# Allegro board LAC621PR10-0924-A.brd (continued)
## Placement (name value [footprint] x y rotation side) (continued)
PC5  -  [C_0805]  34.94 87.39 0 top
PC6  -  [C_0603]  38.95 87.3 270 top
PC7  -  [C_0805]  38.82 84.46 0 top
PC8  -  [C_0402]  277.09 10.93 0 top
PC100  -  [C_0402]  225.92 71.3 180 bottom
PC101  -  [C_0402]  229.78 64.7 0 top
PC102  -  [C_0603]  215.91 73.87 180 bottom
PC103  -  [C_0402]  225.92 71.3 180 top
PC104  -  [C_0805]  226.1 72.67 180 bottom
PC105  -  [C_0805]  226.1 72.67 180 top
PC106  -  [C_0805]  208.67 68.48 180 top
PC107  -  [C_0805]  208.67 71.96 180 top
PC108  -  [C_0805]  208.69 70.21 180 top
PC109  -  [C_0805]  208.7 70.21 180 bottom
PC110  -  [C_0805]  208.67 71.96 180 bottom
PC111  -  [C_0603]  219.42 68.23 270 bottom
PC112  -  [C_0603]  217.44 69.63 90 top
PC113  -  [C_0402]  221.34 68.38 0 bottom
PC114  -  [C_0603]  219.11 65.03 270 bottom
PC115  -  [C_0402]  227.49 64.62 270 bottom
PC116  -  [C_0402]  227.49 64.62 270 top
PC117  -  [C_0805]  226.2 65.21 270 bottom
PC118  -  [C_0805]  226.2 65.21 270 top
PC119  -  [C_0603]  220.31 58.93 270 bottom
PC120  -  [C_0805]  207.38 59.73 270 bottom
PC121  -  [C_0805]  211.03 59.74 270 top
PC122  -  [C_0805]  209.25 59.75 270 bottom
PC123  -  [C_0805]  209.24 59.75 270 top
PC124  -  [C_0805]  207.38 59.74 270 top
PC125  -  [C_0603]  218.83 59.74 90 top
PC126  -  [C_0603]  221.53 58.93 270 bottom
PC127  -  [C_0402]  222.97 58.98 0 bottom
PC128  -  [C_0402]  226.68 59.36 270 bottom
PC201  -  [C_0805]  85.94 55.74 270 top
PC202  -  [C_0805]  84.16 55.74 270 top
PC203  -  [C_0402]  82.76 55.6 270 top
PC204  -  [C_0402]  81.75 55.6 270 top
PC205  -  [C_0603]  87.36 53.06 0 bottom
PC206  -  [C_0603]  90.78 57.53 0 bottom
PC207  -  [C_0603]  92.7 49.29 90 bottom
PC209  -  [C_0603]  96.28 50.82 270 bottom
PC210  -  [C_0402]  91.6 56.75 270 top
PC211  -  [C_0603]  82.47 50.52 0 bottom
PC212  -  [C_0402]  93.28 59.47 180 bottom
PC213  -  [C_0402]  92.39 58.63 90 top
PC214  -  [C_0402]  95.41 53.04 0 bottom
PC215  -  [C_0603]  72.86 50.88 0 bottom
PC216  -  [C_0603]  72.86 48.34 0 top
PC217  -  [C_0603]  72.86 49.61 0 top
PC218  -  [C_0603]  72.86 48.34 0 bottom
PC219  -  [C_0603]  72.86 50.88 0 top
PC220  -  [C_0603]  72.86 49.61 0 bottom
PC301  -  [C_0402]  225.61 57.2 180 bottom
PC302  -  [C_0603]  221.59 55.58 0 bottom
PC303  -  [C_0402]  225.61 57.2 180 top
PC304  -  [C_0603]  226.45 52.34 90 top
PC305  -  [C_0805]  225.77 55.86 180 top
PC306  -  [C_0805]  225.77 55.86 180 bottom
PC307  -  [C_0402]  227.11 48.72 90 bottom
PC308  -  [C_0805]  212.97 51.02 270 bottom
PC309  -  [C_0805]  212.97 51.02 270 top
PC310  -  [C_0805]  211.14 51.01 270 bottom
PC311  -  [C_0805]  211.14 51.01 270 top
PC312  -  [C_0603]  227.29 50.73 270 top
PC313  -  [C_0603]  224.73 49.63 270 top
PC401  -  [C_0402]  200.82 49.69 0 bottom
PC402  -  [C_0402]  205.22 51.36 90 top
PC403  -  [C_0603]  206.68 52.93 270 bottom
PC404  -  [C_0603]  206.68 52.93 270 top
PC406  -  [C_0603]  199.07 56.68 90 bottom
PC407  -  [C_0603]  200.3 56.73 90 bottom
PC408  -  [C_0402]  207.84 53.06 270 top
PC409  -  [C_0402]  207.84 53.05 270 bottom
PC410  -  [C_0402]  204.18 59.38 90 bottom
PC411  -  [C_0402]  203.24 71.15 180 top
PC412  -  [C_0603]  202.52 74.03 0 top
PC413  -  [C_0603]  202.53 74.02 0 bottom
PC415  -  [C_0603]  202.83 63.81 270 bottom
PC416  -  [C_0603]  201.58 63.83 270 bottom
PC417  -  [C_0402]  202.78 75.09 0 bottom
PC418  -  [C_0402]  202.77 75.09 0 top
PC419  -  [C_0402]  204.41 69.07 90 bottom
PC420  -  [C_0402]  198.33 72.39 270 bottom
PC422  -  [C_0603]  200.04 56.7 90 top
PC424  -  [C_0603]  204.06 63.81 270 bottom
PC501  -  [C_0603]  213.87 103.81 0 bottom
PC502  -  [C_0603]  209.27 103.72 0 top
PC503  -  [C_0402]  208.47 101.62 90 bottom
PC504  -  [C_0603]  213.86 103.81 0 top
PC505  -  [C_0402]  208.97 109.06 90 bottom
PC506  -  [C_0402]  211.24 109.01 180 bottom
PC507  -  [C_0402]  217.82 105.98 90 bottom
PC508  -  [C_0805]  222.23 101.29 270 bottom
PC509  -  [C_0402]  219.82 96.43 90 bottom
PC510  -  [C_0402]  219.09 103.84 0 top
PC511  -  [C_0805]  214.88 98.75 90 bottom
PC601  -  [C_0402]  80.15 72.5 90 top
PC602  -  [C_0402]  72.88 68.38 0 top
PC603  -  [C_0603]  79.46 65.51 0 bottom
PC604  -  [C_0603]  79.49 66.76 0 bottom
PC605  -  [C_0402]  75.02 64.72 0 bottom
PC606  -  [C_D]  86.2 72.72 180 bottom
PC608  -  [C_0805]  104 81.17 90 top
PC611  -  [C_0603]  102.89 79.58 180 bottom
PC612  -  [C_0805]  105.78 81.17 90 top
PC613  -  [C_0402]  80 63.96 270 bottom
PC614  -  [C_0402]  82.66 64.85 270 bottom
PC616  -  [C_0402]  81.77 64.85 270 bottom
PC617  -  [C_0402]  77.53 59.64 90 bottom
PC618  -  [C_0402]  77.53 59.64 0 top
PC619  -  [C_0402]  77.53 60.53 0 top
PC620  -  [C_0402]  79.31 59.64 90 top
PC621  -  [C_0402]  76.64 61.42 0 bottom
PC622  -  [C_0603]  109.52 83.42 180 top
PC624  -  [C_0402]  81.19 60.33 90 top
PC625  -  [C_0402]  84.44 64.85 0 bottom
PC626  -  [C_0402]  82.08 60.33 90 top
PC627  -  [C_0402]  82.97 60.33 90 bottom
PC628  -  [C_0402]  81.11 70.69 90 top
PC629  -  [C_0402]  84.47 67.57 270 bottom
PC630  -  [C_0402]  87.84 67.26 270 bottom
PC631  -  [C_0402]  82.89 71.58 180 top
PC632  -  [C_0402]  75.91 70.69 90 bottom
PC633  -  [C_0402]  75.02 70.69 90 top
PC636  -  [C_0402]  85.41 67.57 270 bottom
PC637  -  [C_0402]  75.91 70.69 90 top
PC639  -  [C_0402]  87.84 63.71 0 bottom
PC640  -  [C_0402]  77.48 73.38 270 top
PC641  -  [C_0402]  83.55 63.07 90 bottom
PC642  -  [C_0402]  88.73 66.37 90 top
PC643  -  [C_0402]  83.55 68.66 270 bottom
PC644  -  [C_0402]  74.13 72.47 0 top
PC645  -  [C_0402]  88.73 68.15 180 bottom
PC646  -  [C_0402]  87.84 66.37 90 top
PC647  -  [C_0402]  88.73 65.49 270 top
PC649  -  [C_0402]  81.77 68.66 270 bottom
PC650  -  [C_0402]  78.37 71.61 180 top
PC651  -  [C_0402]  88.73 64.6 180 bottom
PC652  -  [C_0402]  82.66 68.66 270 bottom
PC653  -  [C_0402]  87.84 64.6 90 top
PC654  -  [C_0402]  88.73 65.49 180 bottom
PC655  -  [C_0603]  86.38 77.17 0 bottom
PC656  -  [C_0805]  89.03 71.84 0 top
PC657  -  [C_0805]  89.03 70.06 0 bottom
PC658  -  [C_0805]  89.03 71.84 0 bottom
PC659  -  [C_0402]  89.42 69.65 0 top
PC660  -  [C_0402]  89.42 70.54 0 top
PC661  -  [C_0402]  94.45 76.79 0 bottom
PC662  -  [C_0603]  93.41 71.86 180 bottom
PC671  -  [C_0603]  92 68 0 bottom
PC672  -  [C_0805]  95.43 62.74 0 bottom
PC673  -  [C_0805]  95.43 62.74 0 top
PC677  -  [C_0402]  101.08 67.73 0 bottom
PC678  -  [C_0603]  101.92 66.69 180 bottom
PC679  -  [C_0402]  95.31 61.34 0 bottom
PC680  -  [C_0402]  89.17 73.23 0 top
PC685  -  [C_0402]  100.6 83.62 270 top
PC686  -  [C_0402]  89.17 74.12 0 top
PC688  -  [C_0402]  95.31 61.34 0 top
PC801  -  [C_0805]  71.21 77.93 270 top
PC802  -  [C_0603]  42.2 77.12 270 top
PC803  -  [C_0805]  79.59 77.93 270 top
PC804  -  [C_0805]  83.15 77.93 270 top
PC805  -  [C_0805]  79.59 77.93 270 bottom
PC806  -  [C_0805]  81.37 77.93 270 top
PC807  -  [C_0805]  81.37 77.93 270 bottom
PC808  -  [C_0603]  60.79 87.71 180 top
PC809  -  [C_0402]  57.49 87.96 270 bottom
PC810  -  [C_0402]  59.4 86.57 0 top
PC811  -  [C_0805]  77.81 77.93 270 top
PC812  -  [C_0805]  83.15 77.93 270 bottom
PC813  -  [C_0603]  63.21 84.28 0 bottom
PC814  -  [C_0805]  59.27 84.54 270 bottom
PC815  -  [C_0402]  59.4 89.74 0 top
PC816  -  [C_0402]  60.03 77.8 90 top
PC817  -  [C_0402]  59.02 77.8 90 top
PC818  -  [C_0805]  57.36 77.42 90 top
PC819  -  [C_0805]  57.78 77.47 90 bottom
PC820  -  [C_0805]  56.01 77.47 90 bottom
PC821  -  [C_0603]  60.79 84.15 270 bottom
PC822  -  [C_0805]  55.59 77.42 90 top
PC823  -  [C_0402]  59.26 90.65 90 top
PC824  -  [C_0402]  60.16 90.63 90 top
PC825  -  [C_0603]  76.29 78.06 270 top
PC826  -  [C_0805]  74.76 77.93 270 top
PC827  -  [C_0805]  72.99 77.93 270 top
PC828  -  [C_0603]  69.15 89.98 90 bottom
PC829  -  [C_0402]  68.41 86.06 180 bottom
PC830  -  [C_0402]  66.64 86.06 90 bottom
PC831  -  [C_0402]  67.52 86.95 0 bottom
PC832  -  [C_0603]  61.56 78.06 90 top
PC833  -  [C_0402]  61.58 93.3 90 top
PC834  -  [C_0402]  62.44 94.19 270 top
PC901  -  [C_0402]  29.63 81 180 bottom
PC902  -  [C_0805]  119.86 101.48 0 top
PC903  -  [C_0402]  255.18 95.25 180 top
PC904  -  [C_0402]  76.88 25.05 90 top
PC905  -  [C_0402]  72.35 10.75 90 top
PC906  -  [C_0603]  22.87 76.38 270 top
PC907  -  [C_0603]  29.6 79.96 180 bottom
PC908  -  [C_0603]  25.87 75.71 270 bottom
PC1001  -  [C_0603]  114.51 77.23 90 bottom
PC1002  -  [C_0603]  115.91 70.88 90 top
PC1003  -  [C_0603]  114.51 74.06 90 bottom
PC1004  -  [C_0603]  113.12 74.06 90 top
PC1005  -  [C_0603]  114.51 77.23 90 top
PC1006  -  [C_0603]  111.72 74.06 90 top
PC1007  -  [C_0603]  113.12 70.88 90 top
PC1008  -  [C_0603]  111.72 70.88 90 top
PC1009  -  [C_0603]  114.51 74.06 90 top
PC1010  -  [C_0603]  111.72 77.23 90 top
PC1011  -  [C_0603]  118.71 70.88 90 bottom
PC1012  -  [C_0603]  113.12 70.88 90 bottom
PC1013  -  [C_0603]  111.72 70.88 90 bottom
PC1014  -  [C_0603]  112.58 61.64 90 bottom
PC1015  -  [C_0603]  116.29 66.88 90 bottom
PC1016  -  [C_0603]  117.79 64.18 90 bottom
PC1017  -  [C_0603]  114.08 61.61 90 bottom
PC1018  -  [C_0603]  114.11 64.2 90 bottom
PC1019  -  [C_0603]  112.61 64.2 90 bottom
PC1020  -  [C_0603]  116.29 64.2 90 bottom
PC1021  -  [C_0603]  117.84 66.88 90 bottom
PC1022  -  [C_0603]  114.11 64.2 90 top
PC1023  -  [C_0603]  112.61 64.2 90 top
PC1024  -  [C_0603]  112.58 61.64 90 top
PC1025  -  [C_0603]  114.08 61.61 90 top
PC1026  -  [C_0603]  117.79 64.18 90 top
PC1027  -  [C_0603]  141.92 66.06 270 top
PC1028  -  [C_0603]  143.19 66.03 270 top
PC1029  -  [C_0603]  143.12 70.86 90 top
PC1030  -  [C_0201]  150.05 66.81 0 top
PC1031  -  [C_0201]  152.36 67.52 180 top
PC1032  -  [C_0201]  152.36 66.93 180 top
PC1033  -  [C_0201]  152.36 66.35 180 top
PC1034  -  [C_0201]  152.36 65.76 180 top
PC1035  -  [C_0201]  155.82 64.01 180 top
PC1036  -  [C_0201]  153.53 67.52 0 top
PC1037  -  [C_0201]  153.53 66.93 0 top
PC1038  -  [C_0201]  153.53 66.35 0 top
PC1039  -  [C_0201]  153.53 65.76 0 top
PC1040  -  [C_0201]  148.14 71.33 270 top
PC1041  -  [C_0201]  146.47 70.72 0 top
PC1042  -  [C_0201]  146.01 64.32 0 top
PC1043  -  [C_0201]  146.01 64.9 0 top
PC1044  -  [C_0201]  146.04 65.49 0 top
PC1045  -  [C_0201]  146.04 66.04 0 top
PC1046  -  [C_0201]  146.04 67.9 0 top
PC1047  -  [C_0201]  146.04 68.48 0 top
PC1048  -  [C_0201]  146.04 69.04 0 top
PC1049  -  [C_0201]  146.04 69.6 0 top
PC1050  -  [C_0201]  150.05 66.22 0 top
PC1051  -  [C_0201]  155.82 65.76 180 top
PC1052  -  [C_0201]  155.82 66.35 180 top
PC1053  -  [C_0201]  155.82 64.6 180 top
PC1054  -  [C_0201]  153.53 64.01 0 top
PC1055  -  [C_0201]  146.05 70.16 0 top
PC1056  -  [C_0201]  146 63.73 0 top
PC1057  -  [C_0603]  116.17 85.11 90 bottom
PC1058  -  [C_0603]  117.44 85.11 90 bottom
PC1059  -  [C_0603]  118.71 85.11 90 bottom
PC1060  -  [C_0603]  119.98 85.11 90 bottom
PC1061  -  [C_0603]  155.43 69.65 180 top
PC1062  -  [C_D2]  108.55 71.56 90 bottom
PC1063  -  [C_D2]  109.21 61.27 90 top
PC1064  -  [C_0603]  153.07 69.65 180 top
PC1065  -  [C_0603]  150.71 70.87 180 top
PC1066  -  [C_0603]  155.43 68.43 180 top
PC1067  -  [C_0603]  155.43 72.09 180 top
PC1068  -  [C_0603]  155.43 70.87 180 top
PC1069  -  [C_0603]  153.07 70.87 180 top
PC1070  -  [C_0603]  150.71 69.65 180 top
PC1071  -  [C_0603]  153.07 72.09 180 top
PC1072  -  [C_0603]  120.1 70.88 90 bottom
PC1073  -  [C_0603]  153.07 68.43 180 top
PC1074  -  [C_0603]  150.71 68.43 180 top
PC1075  -  [C_0603]  150.74 72.09 180 top
PC1076  -  [C_0603]  113.12 77.23 90 bottom
PC1077  -  [C_0603]  113.12 74.06 90 bottom
PC1078  -  [C_0603]  111.72 74.06 90 bottom
PC1079  -  [C_0603]  111.72 77.23 90 bottom
PC1080  -  [C_0603]  113.12 77.23 90 top
PC1081  -  [C_0603]  114.51 70.88 90 top
PC1082  -  [C_0603]  114.51 70.88 90 bottom
PC1083  -  [C_0201]  148.86 67.39 180 top
PC1084  -  [C_0201]  148.86 66.81 180 top
PC1085  -  [C_0201]  148.86 65.64 180 top
PC1086  -  [C_0201]  150.05 63.88 0 top
PC1087  -  [C_0201]  148.86 64.47 180 top
PC1088  -  [C_0201]  155.82 66.93 180 top
PC1089  -  [C_0201]  155.82 67.52 180 top
PC1090  -  [C_0201]  152.36 65.18 180 top
PC1091  -  [C_0201]  150.05 65.05 0 top
PC1092  -  [C_0201]  155.82 65.18 180 top
PC1093  -  [C_0201]  148.86 65.05 180 top
PC1094  -  [C_0201]  150.05 67.39 0 top
PC1095  -  [C_0201]  148.86 66.22 180 top
PC1096  -  [C_0201]  150.05 65.64 0 top
PC1097  -  [C_0201]  152.36 64.01 180 top
PC1098  -  [C_0201]  148.86 63.88 180 top
PC1099  -  [C_0201]  152.36 64.6 180 top
PC1125  -  [C_0201]  153.53 65.18 0 top
PC1126  -  [C_0201]  153.53 64.6 0 top
PC1127  -  [C_D2]  108.55 71.56 90 top
PC1128  -  [C_D2]  112.99 58.14 270 bottom
PC1129  -  [C_0603]  144.39 66.03 270 top
PC1130  -  [C_0603]  140.73 66.04 270 top
PC1131  -  [C_0603]  143.29 68.91 270 top
PC1132  -  [C_0603]  140.7 68.91 270 top
PC1133  -  [C_0603]  139.41 66.04 270 top
PC1134  -  [C_0603]  144.59 68.91 270 top
PC1135  -  [C_0603]  145.68 66.93 0 top
PC1136  -  [C_0603]  141.92 70.86 90 top
PC1137  -  [C_0603]  142 68.91 270 top
PC1138  -  [C_0603]  139.38 68.91 270 top
PC1139  -  [C_0603]  115.86 85.16 90 top
PC1140  -  [C_0603]  118.4 85.16 90 top
PC1141  -  [C_0603]  117.13 85.16 90 top
PC1142  -  [C_0603]  120.2 85.92 90 top
PC1143  -  [C_0603]  158.71 69.83 180 top
PC1144  -  [C_0603]  158.29 66.6 0 top
PC1145  -  [C_0603]  158.15 72.29 270 top
PC1146  -  [C_0603]  156.7 72.29 270 top
PC1147  -  [C_0201]  156.42 68.76 270 top
PC1148  -  [C_0201]  158.18 68.76 270 top
PC1149  -  [C_0201]  157.01 68.76 270 top
PC1150  -  [C_0201]  158.76 68.76 270 top
PC1151  -  [C_0201]  159.35 68.76 270 top
PC1152  -  [C_0201]  157.53 66.93 180 top
PC1153  -  [C_0201]  157.59 68.76 270 top
PC1164  -  [C_0201]  150.05 64.47 0 top
PC1170  -  [C_0603]  115.91 70.88 90 bottom
PC1171  -  [C_0603]  117.31 70.88 90 bottom
PC1172  -  [C_0603]  118.71 70.88 90 top
PC1173  -  [C_0603]  117.31 70.88 90 top
PC1174  -  [C_0603]  120.1 70.88 90 top
PC1175  -  [C_0603]  117.84 66.88 90 top
PC1176  -  [C_0603]  114.06 66.88 90 top
PC1177  -  [C_0603]  116.29 64.2 90 top
PC1178  -  [C_0603]  116.29 66.88 90 top
PC1179  -  [C_0603]  112.61 66.88 90 top
PC1180  -  [C_0603]  112.61 66.88 90 bottom
PC1181  -  [C_0603]  114.06 66.88 90 bottom
PC1500  -  [C_0402]  230.8 42.7 0 top
PC1501  -  [C_0805]  230.81 41.3 0 top
PC1502  -  [C_0402]  222.01 43.26 90 top
PC1503  -  [C_0805]  221.97 41.84 180 top
PC1504  -  [C_0402]  229.15 46.64 180 top
PD1  -  [DB3J315E0L_SMINI3-F2-B3]  277.32 12.67 90 top
PD2  -  [TVNST52302AB0_SOT523-3]  57.47 17.15 120 top
PD3  -  [TVNST52302AB0_SOT523-3]  58.51 15.35 120 top
PD4  -  [RB751V-40_SOD323-2]  61.28 14.81 210 top
PD6  -  [PESD5V0U2BT_SOT23-3]  50.96 93.7 270 top
PD7  -  [PESD5V0U2BT_SOT23-3]  52.62 97.54 180 bottom
PD801  -  [SDMK0340L-7-F_SOD323-2]  57.11 83.27 180 top
PD802  -  [SDMK0340L-7-F_SOD323-2]  57.11 84.97 180 top
PD803  -  [SDMK0340L-7-F_SOD323-2]  57.11 83.27 180 bottom
PD901  -  [BAT54CW_SOT323-3]  26.56 90.27 0 top
PD902  -  [PDS5100H-13_POWERDI5-3]  70.73 32 270 top
PD903  -  [PDS5100H-13_POWERDI5-3]  119.84 98.1 0 top
PD904  -  [SDMK0340L-7-F_SOD323-2]  68.44 16.23 270 top
PD905  -  [BAT54CW_SOT323-3]  61.27 11.41 270 top
PH601  -  [R_0402]  98.46 69.04 0 bottom
PH602  -  [R_0402]  97.93 58.97 270 bottom
PH603  -  [R_0402]  92.8 78.26 0 bottom
PH604  -  [R_0402]  114.16 85.86 180 bottom
PH605  -  [R_0402]  102.55 78.06 0 bottom
PJP6  -  [JUMP_43X39]  288.25 41.25 90 top
PJP9  -  [JUMP_43X118]  271.61 43.39 180 top
PJP10  -  [JUMP_43X39]  278.22 44.3 90 top
PJP11  -  [JUMP_43X39]  183.91 64.37 0 top
PJP12  -  [JUMP_43X79]  247.1 35.26 270 top
PJP13  -  [JUMP_43X39]  249.39 53.09 90 top
PJP14  -  [JUMP_43X39]  247.1 91.22 270 top
PJP15  -  [JUMP_43X39]  262.34 48.21 90 top
PJP16  -  [JUMP_43X39]  225.21 33.48 180 top
PJP19  -  [JUMP_43X39]  240.19 49.36 180 top
PJP20  -  [JUMP_43X39]  252.18 44.66 0 top
PJP21  -  [JUMP_43X79]  243.76 42.12 0 top
PJP22  -  [JUMP_43X118]  253.96 38.18 0 top
PJP23  -  [JUMP_43X118]  243.94 52.13 180 top
PJP24  -  [JUMP_43X39]  223.53 90.24 270 bottom
PJP25  -  [JUMP_43X39]  223.83 95.31 180 bottom
PJP26  -  [JUMP_43X79]  256.46 44.78 0 top
PJP27  -  [JUMP_43X39]  162.19 85.17 0 bottom
PJP29  -  [JUMP_43X39]  95.44 83.9 270 bottom
PJP30  -  [JUMP_43X39]  278.24 47.58 270 top
PJP31  -  [JUMP_43X118]  272.14 48.64 180 top
PJP32  -  [JUMP_43X39]  161.89 90.55 90 bottom
PJP33  -  [JUMP_43X39]  225.82 89.2 90 bottom
PJP34  -  [JUMP_43X79]  272.88 14.26 90 top
PJP35  -  [JUMP_43X118]  174.97 87.88 270 bottom
PJP36  -  [JUMP_43X79]  261.33 33.99 270 top
PJP100  -  [JUMP_43X79]  228.65 70.35 90 bottom
PJP101  -  [JUMP_43X79]  226.7 68.12 270 bottom
PJP102  -  [JUMP_43X118]  207.99 66.68 180 bottom
PJP103  -  [JUMP_43X118]  209.28 61.68 90 top
PJP201  -  [JUMP_43X118]  72.73 46.22 270 bottom
PJP202  -  [JUMP_43X79]  84.19 58.55 270 top
PJP203  -  [JUMP_43X39]  88.63 56.16 90 bottom
PJP204  -  [JUMP_43X118]  72.6 46.22 270 top
PJP205  -  [JUMP_43X39]  90.13 58.42 90 top
PJP301  -  [JUMP_43X79]  228.64 59.81 270 top
PJP302  -  [JUMP_43X118]  211.26 52.97 90 bottom
PJP401  -  [JUMP_43X79]  197.65 57.02 180 top
PJP402  -  [JUMP_43X79]  199.78 65.61 180 bottom
PJP403  -  [JUMP_43X39]  207.17 55.25 270 top
PJP404  -  [JUMP_43X39]  200.42 74.6 0 bottom
PJP501  -  [JUMP_43X79]  210.66 100.88 90 top
PJP502  -  [JUMP_43X79]  212.11 102.04 270 bottom
PJP503  -  [JUMP_43X39]  224.82 101.5 180 bottom
PJP504  -  [JUMP_43X39]  212.74 99.03 270 bottom
PJP601  -  [JUMP_43X118]  86.7 78.19 90 top
PJP602  -  [JUMP_43X79]  93.56 64.06 180 bottom
PJP603  -  [JUMP_43X39]  105.04 78.77 270 bottom
PJP801  -  [JUMP_43X118-NPM]  52.16 78.88 270 bottom
PJP805  -  [JUMP_43X39]  268.31 30.51 270 top
PJP1500  -  [JUMP_43X39]  221.35 40.14 270 top
PJP1501  -  [JUMP_43X39]  230.31 38.79 90 top
PJP1603  -  [JUMP_43X39]  267.32 27.61 180 top
PJPDC1  -  [ACES_50290-0050N-001_5P-T]  49.21 86.35 90 bottom
PL1  -  [TAIYO_FBMJ4516HS720NT_2P]  45.93 91.38 180 top
PL2  -  [TAIYO_FBMJ4516HS720NT_2P]  67.66 20.92 90.1 top
PL3  -  [TAIYO_FBMJ4516HS720NT_2P]  65.35 20.87 90.2 top
PL4  -  [MURAT_BLM15AG102SN1D_2P]  54.77 93.41 90 top
PL100  -  [CYNTE_PCMC063T-1R5MN_2P]  216.95 69.73 180 bottom
PL101  -  [CYNTE_PCMC063T-1R5MN_2P]  217.87 60.58 180 bottom
PL201  -  [CYNTE_PCMB063T-1R0MS_2P]  73.05 55.05 0 bottom
PL301  -  [MAG_MMD-05CZ-R68M-X2L_2P]  220.13 51.65 180 bottom
PL402  -  [MAG_MLV-FY12N1R0M-O1L_2P]  199.59 52.47 90 bottom
PL404  -  [MAG_MLV-FY12N1R0M-O1L_2P]  202.37 67.54 270 bottom
PL501  -  [MAG_MLV-FY12N1R0M-O1L_2P]  213.4 107.75 270 bottom
PL601  -  [MAGLA_MMD-05CZ-1R0M-M7L_2P]  109.16 82.5 0 bottom
PL602  -  [KC_FBMA-L11-4532158_2P-NPM]  86.7 76.84 90 top
PL603  -  [MAG_MMD06CZER15MG_4P]  104.27 73.74 180 bottom
PL604  -  [MAG_MMD06CZER15MG_4P]  103.11 55.64 90 bottom
PL801  -  [CYNTE_PCMB063T-3R3MS_2P]  74.54 79.23 180 bottom
PL802  -  [MAGLA_MMD-05CZ-1R0M-M7L_2P]  52.16 76.28 90 bottom
PQ1  -  [IMD2AT-108_SC74-6]  44.08 86.7 0 top
PQ2  -  [SI2301CDS-T1-GE3_SOT23-3]  57.3 12.15 89.7 top
PQ3  -  [FDV301N-G_SOT23-3]  57.42 92.41 0 top
PQ4  -  [MMST3904-7-F_SOT323-3]  59.47 97.06 90 top
PQ5  -  [FDMC6679AZ_MLP8-5]  37.04 85.93 180 top
PQ201  -  [AON6932A_DFN5X6-8-7]  82.03 58.3 0 bottom
PQ501  -  [AON7934_DFN3X3A8-10]  106.22 80.44 180 bottom
PQ801  -  [NTR4502PT1G_SOT23-3]  44.92 77.3 180 top
PQ802  -  [SI4835DDY-T1-GE3_SO8]  39.92 77.19 90 top
PQ803  -  [NTR4502PT1G_SOT23-3]  48.22 77.75 270 top
PQ804  -  [NTR4502PT1G_SOT23-3]  43.06 75.31 180 bottom
PQ805  -  [NTR4502PT1G_SOT23-3]  47.15 75.31 180 bottom
PQ808  -  [AON6932A_DFN5X6-8-7]  63.38 74.88 180 bottom
PQ809  -  [DMN65D8LW-7_SOT323-3]  56.22 89.87 270 top
PQ901  -  [FDS6679AZ-G_SO8]  75.37 22.46 90 top
PQ902  -  [DMN65D8LDW-7_SOT363-6]  255.22 94.25 0 bottom
PQ903  -  [SI4835DDY-T1-GE3_SO8]  68.72 33.58 0 bottom
PQ904  -  [FDS6679AZ-G_SO8]  118.86 101.94 0 bottom
PQ905  -  [FDMC6679AZ_MLP8-5]  76.77 20.27 180 top
PQ906  -  [DMN65D8LW-7_SOT323-3]  37.16 79.52 0 bottom
PQ907  -  [DMN65D8LDW-7_SOT363-6]  71.21 15.83 180 top
PQ908  -  [DMN65D8LW-7_SOT323-3]  75.73 28.36 270 top
PQ909  -  [SI2301CDS-T1-GE3_SOT23-3]  38.07 75.3 180 bottom
PQ910  -  [DMP3099L-7_SOT23-3]  66.13 12.19 90 top
PQ911  -  [DMN65D8LDW-7_SOT363-6]  67.07 15.22 90 top
PR1  -  [R_0402]  36.21 88.7 180 top
PR2  -  [R_0402]  278.84 10.93 0 top
PR3  -  [R_0402]  63.08 16.34 210 top
PR4  -  [R0402_0OHM]  53.37 12.81 89.7 top
PR5  -  [R_0402]  55.33 96.3 0 top
PR6  -  [R_0402]  57.34 98.89 0 top
PR7  -  [R_0402]  56.32 97.24 90 top
PR8  -  [R_0402]  53.53 96.3 0 top
PR9  -  [R_0402]  61.48 97.18 180 top
PR10  -  [R_0402]  51.7 96.3 0 top
PR11  -  [R_0402]  60.59 96.24 0 top
PR12  -  [R_0402]  38.67 83.09 0 top
PR13  -  [R_0805]  40.48 87.75 270 top
PR14  -  [R_0402]  35.21 89.61 180 top
PR15  -  [R_0402]  35.21 90.5 180 top
PR100  -  [R0603_0OHM]  218.27 73.87 180 bottom
PR101  -  [R_0402]  229.75 61.37 0 top
PR102  -  [R_0402]  224.37 68.2 270 bottom
PR103  -  [R_0402]  223.46 68.2 270 bottom
PR104  -  [R0402_0OHM]  219.01 68.15 270 top
PR105  -  [R0402_0OHM]  219.92 68.15 270 top
PR106  -  [R_1206]  215.81 71.86 270 top
PR107  -  [R_0402]  223.46 67.29 90 top
PR108  -  [R_0402]  222.28 67.49 180 bottom
PR109  -  [R_0402]  221.37 67.24 90 top
PR110  -  [R_0402]  222.26 68.15 270 top
PR111  -  [R0603_0OHM]  221.6 65.18 180 bottom
PR112  -  [R_1206]  217.21 62.16 270 top
PR113  -  [R_0402]  226.38 60.38 90 bottom
PR114  -  [R0402_0OHM]  226.07 59.16 180 top
PR115  -  [R_0402]  222.95 58.07 90 top
PR116  -  [R_0402]  225.79 59.36 270 bottom
PR117  -  [R_0402]  223.86 58.07 180 bottom
PR118  -  [R_0402]  223.89 59.01 270 top
PR119  -  [R0402_0OHM]  229.02 58.66 180 bottom
PR120  -  [R0402_0OHM]  227.4 60.93 0 bottom
PR201  -  [R_0603]  93.89 50.69 270 bottom
PR202  -  [R_0603]  87.36 54.33 0 bottom
PR203  -  [R_0402]  89.78 51.03 0 bottom
PR204  -  [R_1206]  78.54 50.4 0 bottom
PR205  -  [R_0603]  95.08 49.42 90 bottom
PR206  -  [R_0402]  93.28 58.58 180 bottom
PR207  -  [R_0402]  96.33 52.15 180 bottom
PR208  -  [R0402_0OHM]  96.33 53.93 180 bottom
PR209  -  [R_0402]  93.28 58.63 90 top
PR210  -  [R0402_0OHM]  96.33 54.82 180 bottom
PR302  -  [R_0402]  222.62 48.98 270 top
PR303  -  [R_1206]  217.75 55.62 0 bottom
PR304  -  [R0603_0OHM]  225.37 53.6 180 top
PR306  -  [R_0402]  226.22 48.7 180 bottom
PR307  -  [R_0402]  223.61 48.66 90 top
PR308  -  [R_0402]  226.22 49.58 180 bottom
PR310  -  [R_0402]  223.53 49.62 270 bottom
PR311  -  [R_0402]  224.42 49.62 270 bottom
PR312  -  [R0402_0OHM]  221.7 48.97 270 top
PR402  -  [R0402_0OHM]  206.13 50.46 180 top
PR403  -  [R_0402]  204.33 51.36 90 top
PR404  -  [R_0402]  204.4 49.07 180 top
PR405  -  [R_0603]  199.78 51.29 270 bottom
PR406  -  [R0402_0OHM]  202.33 72.91 0 top
PR407  -  [R_0402]  203.24 72.04 180 top
PR408  -  [R_0402]  197.3 74.63 0 bottom
PR409  -  [R_0603]  204.53 66.73 90 bottom
PR410  -  [R_0402]  205.4 72.88 270 top
PR411  -  [R_0402]  197.3 73.72 0 bottom
PR412  -  [R0402_0OHM]  203.21 57.53 270 bottom
PR413  -  [R_0402]  205.88 57.53 270 bottom
PR414  -  [R_0402]  207.68 56.42 180 bottom
PR415  -  [R_0402]  204.99 56.65 90 bottom
PR416  -  [R_0402]  206.77 55.53 0 bottom
PR417  -  [R_0402]  197.04 73.08 0 top
PR418  -  [R_0402]  197.04 73.99 0 top
PR419  -  [R_0402]  199.96 72.19 270 top
PR420  -  [R_0402]  200.85 72.19 270 top
PR421  -  [R_0402]  201.36 56.63 0 bottom
PR422  -  [R0402_0OHM]  201.31 57.56 0 bottom
PR423  -  [R0402_0OHM]  198.21 68.86 270 bottom
PR424  -  [R_0402]  198.21 69.73 90 bottom
PR425  -  [R_0402]  204.38 49.98 180 top
PR426  -  [R_0402]  204.49 72.89 270 top
PR427  -  [R0402_0OHM]  203.27 60.29 270 bottom
PR428  -  [R_0402]  197.46 72.39 270 bottom
PR501  -  [R_0402]  209.41 101.62 90 bottom
PR502  -  [R_0603]  213.8 109.03 180 bottom
PR504  -  [R0402_0OHM]  207.78 107.26 90 bottom
PR505  -  [R_0402]  208.05 109.07 90 bottom
PR506  -  [R_0402]  209.21 103.44 180 bottom
PR507  -  [R_0402]  220 102.95 180 top
PR508  -  [R_0402]  220.73 96.4 90 bottom
PR509  -  [R_0402]  218.75 105.98 90 bottom
PR510  -  [R_0402]  221.68 97.43 0 bottom
PR511  -  [R_0402]  222.72 104.07 180 bottom
PR601  -  [R_0402]  72.86 65.69 0 top
PR602  -  [R0402_0OHM]  76.39 67.72 90 top
PR603  -  [R0402_0OHM]  77.35 67.72 90 top
PR604  -  [R_0402]  72.86 66.58 0 top
PR605  -  [R_0402]  72.86 67.49 0 top
PR606  -  [R0402_0OHM]  73.62 66.68 270 bottom
PR607  -  [R0402_0OHM]  75.09 68.79 180 bottom
PR608  -  [R_0402]  79.62 67.8 0 bottom
PR609  -  [R0402_0OHM]  77.38 68.41 180 bottom
PR610  -  [R_0402]  77.53 61.42 0 top
PR611  -  [R_0402]  79.62 68.69 0 bottom
PR612  -  [R_0402]  74.56 63.48 0 bottom
PR613  -  [R_0402]  80.89 63.96 270 bottom
PR614  -  [R0402_0OHM]  74.56 62.59 0 bottom
PR616  -  [R0402_0OHM]  77 63.48 0 bottom
PR617  -  [R_0402]  82.66 63.07 180 bottom
PR618  -  [R_0402]  75.75 65.64 0 bottom
PR619  -  [R_0603]  102.83 80.79 90 bottom
PR620  -  [R0402_0OHM]  77 62.59 0 bottom
PR621  -  [R_0402]  78.42 60.53 0 bottom
PR622  -  [R_0402]  78.42 59.64 0 bottom
PR623  -  [R_0402]  78.42 61.42 0 bottom
PR624  -  [R_0603]  110.4 85.91 90 bottom
PR625  -  [R0402_0OHM]  75.75 66.53 0 bottom
PR626  -  [R_0402]  75.75 67.44 0 bottom
PR627  -  [R_1206]  111.01 80.73 90 top
PR628  -  [R_0402]  97.65 60.77 270 bottom
PR629  -  [R_0402]  84.44 63.96 0 bottom
PR630  -  [R_0402]  82 70.69 0 top
PR631  -  [R_0402]  76.67 60.41 90 top
PR632  -  [R_0402]  81.19 60.33 0 bottom
PR633  -  [R_0402]  82.97 60.33 90 top
PR635  -  [R_0402]  88.73 61.8 180 bottom
PR636  -  [R_0402]  75.02 70.69 180 bottom
PR638  -  [R_0402]  81.19 61.22 0 bottom
PR639  -  [R_0402]  84.47 65.79 0 bottom
PR640  -  [R_0402]  87.84 68.15 0 top
PR641  -  [R_0402]  75.02 71.58 180 bottom
PR642  -  [R_0402]  113.24 86.8 0 bottom
PR643  -  [R_0402]  74.13 71.58 270 top
PR644  -  [R_0402]  88.73 66.37 90 bottom
PR645  -  [R_0402]  88.73 62.82 180 bottom
PR646  -  [R_0402]  79.26 73.38 180 top
PR647  -  [R_0402]  87.82 60.91 0 bottom
PR648  -  [R_0402]  87.84 63.71 270 top
PR649  -  [R_0402]  79.26 72.5 180 top
PR650  -  [R_0402]  88.73 62.82 90 top
PR651  -  [R_0402]  84.47 68.61 0 bottom
PR652  -  [R_0402]  79.26 71.61 0 top
PR656  -  [R_0402]  89.62 66.37 90 top
PR657  -  [R_0402]  100.77 78.06 0 bottom
PR659  -  [R0402_0OHM]  92.85 77.21 90 top
PR660  -  [R_0603]  86.38 75.9 0 bottom
PR661  -  [R_0603]  99.33 74.65 90 top
PR662  -  [R_0402]  88.89 78.16 0 bottom
PR663  -  [R_1206]  95.57 70.21 180 bottom
PR671  -  [R0402_0OHM]  99.38 68.13 180 top
PR672  -  [R_0603]  92 66.73 0 bottom
PR674  -  [R_0603]  98.72 61.31 270 bottom
PR676  -  [R_1206]  105.76 67.1 180 bottom
PR678  -  [R_0402]  76.8 64.72 0 bottom
PR679  -  [R0402_0OHM]  102 84.48 180 bottom
PR680  -  [R_0402]  95.41 68 0 top
PR801  -  [R_0402]  56.6 87.96 90 top
PR802  -  [R_1206_4P-D]  48.98 81.87 180 top
PR803  -  [R_0402]  39.64 82.2 0 top
PR804  -  [R0402_0OHM]  41.26 74.71 0 top
PR805  -  [R_0402]  54.82 87.08 90 bottom
PR806  -  [R0402_0OHM]  55.71 87.96 0 bottom
PR807  -  [R0402_0OHM]  55.71 87.08 0 bottom
PR808  -  [R_0402]  43.47 79.23 180 bottom
PR809  -  [R_0402]  47.71 79.15 180 bottom
PR810  -  [R0402_0OHM]  40.58 76.58 90 bottom
PR811  -  [R_1206]  54.82 85.17 0 bottom
PR812  -  [R_0402]  56.6 88.85 0 bottom
PR813  -  [R_0402]  59.4 88.85 0 top
PR814  -  [R_0603]  62.06 84.15 270 bottom
PR815  -  [R0402_0OHM]  57.49 89.87 270 top
PR816  -  [R0402_0OHM]  56.6 90.12 0 bottom
PR817  -  [R_0402]  55.71 88.09 180 top
PR818  -  [R_0402]  61.56 93.3 270 bottom
PR819  -  [R0402_0OHM]  56.6 91.01 0 bottom
PR820  -  [R0402_0OHM]  56.6 91.9 0 bottom
PR821  -  [R_0402]  66.64 85.17 0 bottom
PR822  -  [R_0402]  61.05 90.63 90 top
PR823  -  [R_1206_4P-D]  73.62 79.71 0 top
PR824  -  [R_1206]  63.08 78.19 0 top
PR825  -  [R_0402]  66.64 87.84 0 bottom
PR826  -  [R_0603]  66.66 89.26 0 bottom
PR827  -  [R_0402]  67.22 91.42 270 bottom
PR828  -  [R0402_0OHM]  64.22 93.3 270 bottom
PR829  -  [R_0402]  68.11 90.5 90 bottom
PR830  -  [R_0402]  59.83 94.19 270 top
PR831  -  [R_0402]  60.69 94.19 270 top
PR832  -  [R_0402]  61.61 92.41 0 top
PR833  -  [R0402_0OHM]  64.22 93.3 180 top
PR834  -  [R_0402]  63.33 92.41 0 top
PR835  -  [R0402_0OHM]  63.33 93.3 270 bottom
PR836  -  [R0402_0OHM]  62.44 93.3 270 bottom
PR837  -  [R_0402]  53.17 90.15 270 top
PR901  -  [R0402_0OHM]  31.69 84.41 0 top
PR902  -  [R_0402]  258.48 94.31 180 bottom
PR903  -  [R_0402]  253.91 93.66 270 bottom
PR904  -  [R_0402]  257.64 93.37 270 bottom
PR905  -  [R_0402]  253.35 94.49 270 top
PR906  -  [R0402_0OHM]  122.59 101.17 0 top
PR907  -  [R0402_0OHM]  253.35 91.82 90 top
PR908  -  [R_0402]  117.66 97.84 270 bottom
PR909  -  [R_0402]  72.35 13.42 270 top
PR910  -  [R_0402]  77.84 25.95 270 top
PR911  -  [R_0402]  62.39 11.97 270 top
PR912  -  [R_0402]  76.88 26.89 90 top
PR913  -  [R0402_0OHM]  38.95 80.95 270 bottom
PR914  -  [R_0402]  68.79 10.88 90 top
PR915  -  [R_0402]  39.09 79.12 180 bottom
PR916  -  [R_0402]  37.31 82.57 180 bottom
PR917  -  [R_0402]  65.65 17.68 0 top
PR918  -  [R0402_0OHM]  28.74 74.83 90 top
PR919  -  [R0402_0OHM]  64.17 16.74 270 top
PR920  -  [R_0402]  25.69 75.77 270 top
PR921  -  [R_0805]  24.37 74.6 90 top
PR922  -  [R0402_0OHM]  24.98 86.24 90 top
PR923  -  [R0402_0OHM]  26.61 74.86 90 top
PR924  -  [R_0603]  24.13 81.13 0 bottom
PR925  -  [R_0402]  28.33 90.46 0 top
PR926  -  [R0402_0OHM]  27.65 86.24 90 top
PR927  -  [R_0402]  28.54 86.24 90 top
PR928  -  [R_0603]  27.67 74.53 90 top
PR929  -  [R_0402]  25.87 87.15 270 top
PR930  -  [R0402_0OHM]  23.63 86.24 90 top
PR931  -  [R0402_0OHM]  31.69 85.3 0 top
PR932  -  [R0402_0OHM]  30.82 76.25 180 top
PR933  -  [R_0603]  24.14 82.35 0 bottom
PR934  -  [R_0402]  29.78 83.11 180 bottom
PR935  -  [R_0603]  25.51 79.86 180 bottom
PR936  -  [R_0402]  62.39 12.83 90 top
PR937  -  [R0402_0OHM]  22.74 86.24 90 top
PR938  -  [R0402_0OHM]  26.76 86.24 90 top
PR939  -  [R_0603]  32.24 81.59 270 top
PR1500  -  [R_0402]  230.03 47.58 270 top
PR1501  -  [R_0402]  221.09 43.23 90 top
PR1502  -  [R_0402]  229.12 47.55 180 top
PR1503  -  [R_0402]  221.09 45.09 0 top
PRP1  -  [RP_0804_8P4R]  60.46 17.96 30 top
PU1  -  [TS5A63157DCKR_SC70-6]  54.22 97.67 90 top
PU100  -  [SY8286BRAC_QFN20_3X3]  220.28 72.93 270 bottom
PU101  -  [TC7SH08FU_SSOP5]  228.59 63.66 270 top
PU102  -  [SY8286CRAC_QFN20_3X3]  222.01 63.63 270 bottom
PU201  -  [RT8207PGQW_WQFN20_3X3]  91.68 55.86 0 bottom
PU301  -  [SYX196DQNC_QFN10_3X3]  223.34 51.54 0 bottom
PU401  -  [TPS62134CRGT_QFN16_3X3]  201.98 52.34 0 bottom
PU402  -  [TPS62134ARGT_QFN16_3X3]  202.22 69.07 90 bottom
PU501  -  [SY8032ABC_SOT23-6]  209.17 107.66 0 bottom
PU502  -  [APL5930KAI-TRG_SO8]  220.36 98.91 180 bottom
PU602  -  [ISL62883CHRTZ-T_TQFN40_5X5]  80.63 63.2 0 top
PU603  -  [CSD97374CQ4M_SON8_3P5X4P5]  92.9 76.86 270 bottom
PU605  -  [CSD97374CQ4M_SON8_3P5X4P5]  99.15 67.69 270 bottom
PU606  -  [ISL95808HRZ-TS2378_DFN8_2X2]  101.55 81.02 180 bottom
PU801  -  [BQ24715URUYR_WQFN28_4X4]  59.65 87.33 0 bottom
PU901  -  [CD3301RHHR_QFN36_6X6]  24.68 78.39 0 top
PU902  -  [TC7SH08FU_SSOP5]  254.39 92.28 0 top
PU903  -  [TC7SH08FU_SSOP5]  71.21 12.78 180 top
PU1500  -  [APL5930KAI-TRG_SO8]  223.73 45.39 270 top
QA1  -  [L2N7002WT1G_SC-70-3]  273.77 25.35 270 top
QA2  -  [DMN65D8LDW-7_SOT363-6]  290.15 42.39 270 top
QA3  -  [DMN65D8LDW-7_SOT363-6]  277.36 22.75 90 top
QC2  -  [DMN65D8LDW-7_SOT363-6]  195.54 51.77 0 top
QC3  -  [L2N7002WT1G_SC-70-3]  184.9 41.49 0 top
QE2  -  [DMN65D8LDW-7_SOT363-6]  252.52 68.07 0 top
QE3  -  [MMBT3904WT1G_SC70-3]  141.09 61.11 0 top
QE4  -  [MMBT3904WT1G_SC70-3]  132.55 84.34 0 bottom
QE5  -  [MMBT3904WT1G_SC70-3]  254.75 16.55 180 top
QE6  -  [MMBT3904WT1G_SC70-3]  99.82 69.75 270 top
QE7  -  [MMBT3904WT1G_SC70-3]  154.69 24.95 270 bottom
QE11  -  [L2N7002WT1G_SC-70-3]  131.78 88.91 180 bottom
QL1  -  [DMN65D8LDW-7_SOT363-6]  281.03 76.45 90 bottom
QL2  -  [DMN65D8LDW-7_SOT363-6]  282.93 80.31 270 bottom
QN1  -  [DMN65D8LDW-7_SOT363-6]  282.03 19.64 180 top
QR1  -  [L2N7002WT1G_SC-70-3]  266.09 45.83 90 top
QV1  -  [AO6405_TSOP6]  91.56 83.68 270 bottom
QV2  -  [L2N7002WT1G_SC-70-3]  90.89 80.41 180 top
QV3  -  [DMN65D8LDW-7_SOT363-6]  108.56 92.88 180 bottom
QV4  -  [L2N7002WT1G_SC-70-3]  76.67 96.92 180 top
QV5  -  [L2N7002WT1G_SC-70-3]  94.06 96.4 0 top
QV7  -  [L2N7002WT1G_SC-70-3]  96.55 96.4 0 top
QV8  -  [LP2301ALT1G_SOT23-3]  116.06 90.81 180 bottom
QV9  -  [L2N7002WT1G_SC-70-3]  129.91 90.9 0 bottom
QV10  -  [L2N7002WT1G_SC-70-3]  141.95 90.53 180 bottom
QV11  -  [L2N7002WT1G_SC-70-3]  200.94 91.27 270 bottom
QZ1  -  [LP2301ALT1G_SOT23-3]  112.79 93.93 270 bottom
QZ3  -  [DMN65D8LDW-7_SOT363-6]  285.23 69.98 180 bottom
QZ4  -  [DDTA114EUA-7-F_SOT323-3]  284.55 74.72 0 bottom
QZ7  -  [DMN65D8LDW-7_SOT363-6]  287.33 69.75 0 bottom
QZ9  -  [LP2301ALT1G_SOT23-3]  196.05 62.68 270 top
R6  -  [R_0402]  156.93 107.19 90 top
R41  -  [R_0402]  155.15 108.11 270 top
R252  -  [R_0402]  138.26 94.87 90 bottom
R253  -  [R_0402]  139.28 94.87 90 bottom
R254  -  [R_0402]  137.76 109.5 270 top
R255  -  [R_0402]  140.17 94.87 90 bottom
R256  -  [R_0402]  138.64 109.5 270 top
R257  -  [R_0402]  141.18 94.87 90 bottom
R258  -  [R_0402]  141.31 109.5 270 top
R259  -  [R_0402]  137.37 94.87 90 bottom
R260  -  [R_0402]  135.98 109.5 270 top
R261  -  [R_0402]  136.87 109.5 270 top
R262  -  [R_0402]  139.53 109.5 270 top
R263  -  [R_0402]  142.07 94.87 90 bottom
R264  -  [R_0402]  140.42 109.5 270 top
R265  -  [R_0402]  143.09 94.87 90 bottom
R266  -  [R_0402]  143.98 94.87 90 bottom
R267  -  [R_0402]  142.2 109.5 270 top
R268  -  [R_0402]  145.53 95.89 270 bottom
R271  -  [R_0402]  143.5 108.46 0 top
R272  -  [R_0402]  168.74 108.46 90 top
R273  -  [R_0402]  163.36 101.04 0 top
R274  -  [R0603_0OHM]  267.8 43.54 180 top
RA1  -  [R_0402]  295.74 28.53 180 top
RA2  -  [R_0402]  269.71 26.57 270 top
RA3  -  [R0603_0OHM]  283.93 42.88 270 top
RA4  -  [R0603_0OHM]  286.47 42.37 270 top
RA5  -  [R_0402]  289.06 33.48 0 top
RA6  -  [R_0402]  289.11 34.37 0 top
RA7  -  [R_0402]  284.57 34.81 0 top
RA8  -  [R_0402]  284.57 33.92 0 top
RA9  -  [R_0402]  270.98 29.89 90 top
RA12  -  [R_0402]  272.46 28.03 180 top
RA13  -  [R_0402]  272.46 27.14 180 top
RA14  -  [R_0402]  274.41 37.04 270 top
RA17  -  [R_0402]  273.21 32.92 180 top
RA18  -  [R_0402]  273.55 36.47 180 top
RA21  -  [R_0402]  293.05 42.47 270 top
RA24  -  [R_0402]  281.01 25.3 270 top
RA25  -  [R_0402]  282.03 25.3 270 top
RA26  -  [R_0402]  272.76 22.69 90 top
RA27  -  [R_0402]  275.8 26.06 270 top
RA28  -  [R_0402]  274.92 26.06 270 top
RA29  -  [R_0402]  278.76 24.17 270 top
RA30  -  [R_0402]  277.41 27.38 90 top
RA31  -  [R_0402]  278.31 27.41 90 top
RA32  -  [R_0402]  279.2 27.41 90 top
RA35  -  [R0402_0OHM]  295.62 22.79 0 top
RA36  -  [R0402_0OHM]  285.71 25.35 270 top
RA37  -  [R0402_0OHM]  285.41 41.38 90 top
RA38  -  [R_0402]  276.69 25.99 0 top
RA39  -  [R0805_0OHM]  272.16 39.93 0 top
RA44  -  [R_0402]  284.19 28.27 270 top
RA45  -  [R0402_0OHM]  284.69 25.3 270 top
RC1  -  [R_0402]  167.73 69.4 90 top
RC2  -  [R_0402]  144.18 71.4 90 top
RC3  -  [R_0402]  174.33 85.42 0 top
RC4  -  [R_0402]  183.12 57.97 0 bottom
RC5  -  [R_0402]  162.19 60.56 90 top
RC6  -  [R_0402]  161.61 46.33 270 top
RC7  -  [R_0402]  162.47 46.33 270 top
RC10  -  [R_0402]  195.46 48.67 180 bottom
RC11  -  [R_0402]  195.46 49.69 180 bottom
RC12  -  [R_0402]  179.7 67.99 270 top
RC13  -  [R_0402]  170.14 45.34 90 top
RC14  -  [R_0402]  178.79 67.96 270 top
RC15  -  [R_0402]  178.32 68.91 0 bottom
RC16  -  [R_0402]  178.07 43.79 270 top
RC17  -  [R_0402]  178.32 69.8 0 bottom
RC18  -  [R_0402]  177.13 43.79 270 top
RC19  -  [R_0402]  178.19 66.25 0 bottom
RC20  -  [R_0402]  178.19 67.14 0 bottom
RC21  -  [R_0402]  171.03 45.34 90 top
RC22  -  [R_0402]  178.88 46.03 270 top
RC23  -  [R_0402]  167.99 67.2 90 top
RC24  -  [R_0402]  179.77 46.03 270 top
RC25  -  [R_0402]  178.32 68.03 0 bottom
RC26  -  [R_0402]  175.73 43.39 180 top
RC27  -  [R_0402]  172.88 43.49 180 top
RC28  -  [R_0402]  193 56.67 270 top
RC29  -  [R_0402]  194.98 66.12 180 top
RC30  -  [R_0402]  196.28 71.01 90 bottom
RC31  -  [R_0402]  191.58 49.98 90 top
RC32  -  [R_0402]  203.67 46.82 0 top
RC33  -  [R_0402]  203.69 47.78 0 top
RC34  -  [R_0402]  206.34 46.82 0 top
RC35  -  [R_0402]  206.29 48.26 0 top
RC36  -  [R_0402]  208.39 48.26 0 top
RC37  -  [R0402_0OHM]  189.7 71.91 90 bottom
RC38  -  [R_0402]  210.02 46.82 0 top
RC39  -  [R_0402]  196.38 73.33 90 bottom
RC40  -  [R_0402]  211.16 47.83 0 top
RC41  -  [R0402_0OHM]  213.32 46.82 180 top
RC42  -  [R_0402]  192.14 59.1 180 top
RC43  -  [R_0402]  194.07 59.38 180 top
RC44  -  [R_0402]  183.25 68.44 0 top
RC45  -  [R_0402]  181.17 71.57 0 top
RC46  -  [R_0402]  153.53 82.2 180 bottom
RC47  -  [R_0402]  172.81 45.34 90 top
RC48  -  [R_0402]  175.73 44.28 180 top
RC50  -  [R_0402]  171.11 43.49 180 top
RC51  -  [R_0402]  171.11 44.38 180 top
RC52  -  [R_0402]  155.97 86.25 0 top
RC54  -  [R_0402]  179.32 61.41 0 bottom
RC56  -  [R_0402]  188.56 46.24 270 top
RC57  -  [R_0402]  186.55 46.21 270 top
RC59  -  [R_0402]  171.11 42.6 180 top
RC60  -  [R_0402]  188.25 69.55 180 bottom
RC61  -  [R0402_0OHM]  186.37 69.96 270 bottom
RC62  -  [R0402_0OHM]  185.48 69.96 270 bottom
RC64  -  [R0402_0OHM]  188.72 71.4 270 bottom
RC65  -  [R_0402]  187.04 65.62 0 bottom
RC67  -  [R_0402]  217.74 46.56 0 top
RC68  -  [R_0402]  219.54 45.67 90 top
RC69  -  [R_0402]  166.97 46.31 180 top
RC71  -  [R_0402]  128.15 86.82 180 bottom
RC72  -  [R_0402]  167.85 45.42 270 top
RC73  -  [R_0402]  184.8 59.08 90 top
RC74  -  [R_0402]  189.78 48.72 180 top
RC75  -  [R_0402]  181.32 39.7 180 top
RC76  -  [R_0402]  261.46 53.8 270 top
RC77  -  [R_0402]  121.37 86.19 270 bottom
RC78  -  [R_0402]  127.27 85.98 270 bottom
RC79  -  [R_0402]  128.97 86.82 0 bottom
RC80  -  [R_0402]  128.99 85.96 0 bottom
RC81  -  [R_0402]  142.86 85.96 180 bottom
RC82  -  [R_0402]  142.84 84.2 270 bottom
RC83  -  [R_0402]  125.49 86.82 90 bottom
RC84  -  [R_0402]  126.4 85.99 270 bottom
RC86  -  [R_0402]  132.51 86.34 270 top
RC87  -  [R_0402]  141.95 85.07 0 bottom
RC88  -  [R_0402]  165.19 46.31 270 top
RC89  -  [R_0402]  164.3 46.31 270 top
RC90  -  [R_0402]  139.2 69.98 0 top
RC91  -  [R_0402]  139.2 70.87 0 top
RC92  -  [R_0402]  164.93 42.52 90 top
RC93  -  [R_0402]  161.35 44.53 0 top
RC94  -  [R_0402]  164.04 42.52 90 top
RC95  -  [R_0402]  163.13 43.48 90 top
RC96  -  [R_0402]  182.42 68.44 180 top
RC109  -  [R_0402]  123.4 73.28 0 bottom
RC110  -  [R_0402]  124.22 86.26 270 bottom
RC112  -  [R_0402]  123.23 86.24 270 bottom
RC113  -  [R_0402]  125.53 85.99 270 bottom
RC114  -  [R_0402]  139.33 72.29 0 top
RC115  -  [R_0402]  89.8 49 180 bottom
RC120  -  [R_0402]  128.15 85.07 90 bottom
RC121  -  [R_0402]  86.51 34.77 90 top
RC122  -  [R_0402]  87.93 34.69 0 top
RC123  -  [R_0402]  85.69 38.92 90 top
RC124  -  [R_0402]  87.11 37.04 180 top
RC126  -  [R_0402]  90.13 39.83 0 top
RC128  -  [R_0402]  93.51 38.05 180 top
RC129  -  [R_0402]  93.51 38.94 180 top
RC130  -  [R_0402]  141.97 84.2 270 bottom
RC131  -  [R_0402]  103.52 41.48 0 top
RC132  -  [R_0402]  91.38 38.94 180 top
RC133  -  [R_0402]  92.59 37.19 0 top
RC134  -  [R_0402]  103.52 40.59 0 top
RC135  -  [R_0402]  101.21 39.2 0 top
RC136  -  [R_0402]  141.97 86.3 270 top
RC137  -  [R_0402]  98.69 48.52 0 top
RC138  -  [R_0402]  82.54 39.91 180 top
RC139  -  [R_0402]  94.75 39.02 90 top
RC140  -  [R_0402]  120.61 70.01 270 top
RC141  -  [R_0402]  121.5 69.09 90 top
RC143  -  [R0603_0OHM]  165.82 85.55 90 top
RC152  -  [R_0402]  128.99 85.09 0 bottom
RC153  -  [R_0402]  130.87 82.22 90 bottom
RC157  -  [R_0402]  129.93 83.14 270 bottom
RC161  -  [R_0402]  124.29 69.73 90 bottom
RC163  -  [R_0402]  123.33 71.43 90 bottom
RC165  -  [R_0402]  157.01 65.21 0 top
RC166  -  [R_0402]  160.49 72.32 180 top
RC167  -  [R_0402]  160.39 61.29 0 top
RC168  -  [R_0402]  159.52 70.92 0 top
RC169  -  [R0603_0OHM]  167.6 82.31 90 bottom
RC170  -  [R0402_0OHM]  160.78 85.27 270 bottom
RC171  -  [R0402_0OHM]  159.93 86.31 180 bottom
RC173  -  [R0402_0OHM]  159.9 85.27 270 bottom
RC175  -  [R_0402]  178.8 70.64 0 top
RC176  -  [R_0402]  184.09 71.71 270 top
RC177  -  [R_0402]  184.97 71.71 270 top
RC178  -  [R_0402]  178.8 69.75 0 top
RC179  -  [R_0402]  145.12 71.4 90 top
RC180  -  [R_0402]  143.85 85.41 180 top
RC181  -  [R_0402]  205.17 91.37 270 bottom
RC182  -  [R_0402]  203.92 91.37 270 bottom
RC183  -  [R_0402]  188.3 57.23 180 top
RC184  -  [R_0402]  188.3 59.01 180 top
RC186  -  [R_0402]  188.3 58.12 180 top
RC187  -  [R_0402]  166.51 41.46 90 top
RC189  -  [R_0402]  171.92 45.34 90 top
RC190  -  [R_0402]  171.97 44.38 0 top
RC194  -  [R_0805]  198.97 61.21 90 bottom
RC211  -  [R0402_0OHM]  189.29 56.32 180 top
RC212  -  [R_0402]  188.81 62.64 270 bottom
RC214  -  [R0402_0OHM]  180.59 60.57 180 top
RC215  -  [R_0402]  178.37 39.7 0 top
RC216  -  [R0603_0OHM]  88.99 37.8 90 top
RC217  -  [R_0402]  90.46 38.05 0 top
RC218  -  [R_0402]  91.02 36.28 180 top
RC219  -  [R_0402]  91.02 37.16 180 top
RC220  -  [R_0402]  176.87 41.15 0 top
RC221  -  [R0402_0OHM]  244.94 96.52 90 bottom
RC222  -  [R_0402]  244.94 94.49 90 bottom
RC223  -  [R_0402]  165.82 43.56 90 top
RC224  -  [R_0402]  178.98 86.95 180 bottom
RC225  -  [R_0402]  178.01 91.06 90 bottom
RC227  -  [R_0402]  178.95 91.9 0 bottom
RC228  -  [R0402_0OHM]  103.52 43.59 270 top
RC229  -  [R0402_0OHM]  103.53 39.61 0 top
RC230  -  [R0402_0OHM]  102.43 37.79 0 top
RC231  -  [R0402_0OHM]  150.41 63.07 0 top
RC234  -  [R_0402]  178.78 65.36 270 top
RC235  -  [R0402_0OHM]  179.67 65.36 270 top
RC236  -  [R_0402]  180.51 85.41 180 top
RC237  -  [R_0402]  185.69 59.11 90 top
RC238  -  [R_0603]  161.38 89.3 270 bottom
RC239  -  [R_0402]  83.58 38.48 90 top
RC240  -  [R_0402]  84.47 38.48 90 top
RC241  -  [R_0402]  86.6 38.89 90 top
RC242  -  [R_0402]  190.23 87.28 90 top
RC243  -  [R_0402]  218.65 45.67 180 top
RC244  -  [R0402_0OHM]  187.41 71.4 270 bottom
RC246  -  [R_0402]  180.71 72.69 270 bottom
RC267  -  [R_0402]  183.12 66.68 180 bottom
RC268  -  [R_0402]  180.15 69.87 270 bottom
RC270  -  [R_0402]  184.78 60.21 270 bottom
RC272  -  [R_0402]  183.2 45.11 90 top
RC276  -  [R_0402]  214.16 47.71 0 top
RC279  -  [R_0402]  171.97 42.6 0 top
RC281  -  [R_0402]  244.69 86.24 90 bottom
RC282  -  [R_0402]  186.55 60.02 270 top
RC283  -  [R_0402]  183.55 63.2 180 bottom
RC287  -  [R_0402]  181.57 64.93 0 bottom
RC288  -  [R_0402]  183.22 43.64 270 top
RC289  -  [R0402_0OHM]  214.16 46.82 0 top
RC290  -  [R0402_0OHM]  180.73 91.9 0 bottom
RC291  -  [R_0402]  178.98 87.84 180 bottom
RC292  -  [R_0402]  182.49 65.79 180 bottom
RC295  -  [R0402_0OHM]  154.37 82.2 0 bottom
RC296  -  [R0402_0OHM]  179.32 60.52 0 bottom
RC297  -  [R_0402]  148.02 85.4 90 top
RC298  -  [R_0402]  149.01 85.4 90 top
RC299  -  [R0603_0OHM]  179.76 72.79 180 bottom
RC300  -  [R0402_0OHM]  169.8 83.26 270 bottom
RC301  -  [R0402_0OHM]  179.23 70.69 180 bottom
RC302  -  [R0402_0OHM]  168.64 83.25 270 bottom
RC303  -  [R0402_0OHM]  164.07 87.68 180 bottom
RC307  -  [R0402_0OHM]  181.57 65.79 270 top
RC308  -  [R0402_0OHM]  180.68 65.79 270 top
RC309  -  [R0603_0OHM]  173.06 83.72 270 bottom
RC310  -  [R0603_0OHM]  163.88 70.51 180 top
RC311  -  [R_0402]  165.57 60.41 270 top
RC312  -  [R_0402]  179.72 68.87 180 top
RC313  -  [R_0402]  178.2 64.48 0 bottom
RC316  -  [R_0402]  191.22 53.24 270 top
RC317  -  [R_0402]  185.61 42.69 180 top
RC318  -  [R_0402]  196.28 53.99 0 bottom
RC319  -  [R_0402]  196.28 53.1 0 bottom
RC320  -  [R_0402]  169.12 92.13 270 bottom
RC322  -  [R_0402]  182.01 70.69 270 top
RC323  -  [R_0402]  257.16 91.22 0 top
RC324  -  [R_0402]  148.37 72.32 180 top
RC325  -  [R0402_0OHM]  186.02 63.77 90 bottom
RC326  -  [R_0402]  186.63 40.96 270 top
RC327  -  [R0402_0OHM]  186.63 42.79 270 top
RC328  -  [R0402_0OHM]  130.63 85.54 0 top
RC330  -  [R_0402]  32.46 77.52 90 bottom
RC331  -  [R_0402]  34.4 77.52 90 bottom
RC335  -  [R_0402]  34.41 80.63 270 bottom
RC336  -  [R_0402]  32.47 80.64 270 bottom
RC337  -  [R0402_0OHM]  165.81 67.26 180 top
RC338  -  [R_0402]  164.25 62.58 270 top
RC339  -  [R_0402]  183.15 38.37 0 top
RC340  -  [R_0402]  183.15 39.59 90 top
RC341  -  [R_0402]  182.06 71.36 0 bottom
RC342  -  [R_0402]  181.47 69.66 270 bottom
RC343  -  [R_0402]  184.33 61.13 90 top
RC344  -  [R_0402]  248.85 52.14 180 bottom
RC346  -  [R_0402]  229.23 59.69 0 bottom
RC347  -  [R_0402]  183.8 66.83 270 top
RC348  -  [R_0402]  182.9 66.83 270 top
RD2  -  [R_0402]  80.56 11.76 180 top
RD4  -  [R_0402]  194.58 11.31 90 top
RD18  -  [R_0402]  120.26 12.2 0 top
RD19  -  [R_0402]  122.03 11.31 90 top
RD20  -  [R_0402]  121.17 11.31 180 top
RD21  -  [R_0402]  122.95 13.08 90 top
RD22  -  [R_0402]  75.12 13.87 270 top
RD24  -  [R_0402]  74.74 11.61 270 top
RD25  -  [R_0402]  73.85 11.61 270 top
RD29  -  [R0402_0OHM]  79.08 12.65 0 top
RD30  -  [R_0402]  78.98 13.52 90 top
RD60  -  [R0603_0OHM]  230.47 14.75 90 top
RD61  -  [R_0402]  112.23 11.38 90 top
RD62  -  [R_0402]  147.92 14.76 270 top
RD63  -  [R_0402]  147.92 12.07 90 top
RD64  -  [R_0402]  124.78 11.33 180 top
RD65  -  [R0603_0OHM]  148.53 18.81 90 top
RD66  -  [R0402_0OHM]  147.03 13.85 90 top
RD67  -  [R0402_0OHM]  147.03 12.98 270 top
RD68  -  [R0402_0OHM]  123.86 12.22 0 top
RD69  -  [R_0402]  229.65 13.8 180 top
RD70  -  [R0402_0OHM]  229.65 12.02 180 top
RD71  -  [R_0402]  205.57 12.22 270 top
RD72  -  [R0402_0OHM]  228.74 12.91 0 top
RD73  -  [R_0402]  228.74 11.13 0 top
RD74  -  [R0402_0OHM]  204.68 11.31 90 top
RD75  -  [R_0402]  74.23 13.01 90 top
RE11  -  [R_0402]  246.65 88.22 0 bottom
RE12  -  [R_0402]  244.94 73.66 90 top
RE17  -  [R_0402]  239.41 80.34 0 top
RE20  -  [R_0402]  244.94 71.89 90 top
RE21  -  [R_0402]  256.6 73.66 90 top
RE24  -  [R_0402]  239.1 83.65 270 top
RE25  -  [R_0402]  258.58 75.52 90 top
RE26  -  [R_0402]  257.69 75.52 90 top
RE27  -  [R_0402]  242.1 81.23 180 top
RE31  -  [R_0402]  277.55 50.91 90 top
RE32  -  [R0402_0OHM]  275.07 51.36 90 top
RE33  -  [R_0402]  278.44 51.83 270 top
RE35  -  [R_0402]  248.5 87.25 90 bottom
RE36  -  [R_0402]  257.16 60.96 0 top
RE38  -  [R_0402]  251.04 72.52 90 top
RE42  -  [R_0402]  273.26 52.63 270 top
RE48  -  [R_0402]  265.77 69.63 270 top
RE51  -  [R_0402]  263.96 72.15 270 top
RE55  -  [R_0402]  263.08 72.15 270 top
RE56  -  [R_0402]  257.01 63.06 0 top
RE57  -  [R_0402]  267.93 49.58 270 top
RE58  -  [R_0402]  267.07 49.58 270 top
RE59  -  [R0402_0OHM]  259.93 54.31 270 top
RE60  -  [R_0402]  253.96 55.25 90 top
RE62  -  [R_0402]  274.18 51.36 90 top
RE63  -  [R_0402]  255.46 60.33 180 top
RE64  -  [R_0402]  268.79 49.58 270 top
RE65  -  [R_0402]  254.64 58.05 0 top
RE66  -  [R_0402]  262.47 68.71 90 top
RE67  -  [R_0402]  250.26 68.79 0 top
RE68  -  [R_0402]  252.46 71.05 0 top
RE69  -  [R_0402]  135.88 90.54 180 bottom
RE70  -  [R_0402]  131.35 85.88 0 bottom
RE71  -  [R_0402]  295.41 40.44 0 top
RE72  -  [R_0402]  295.36 44.28 0 top
RE73  -  [R_0402]  295.31 46.31 0 top
RE74  -  [R_0402]  295.31 47.33 0 top
RE75  -  [R_0402]  295.36 45.3 0 top
RE77  -  [R_0402]  269.4 68.79 180 top
RE78  -  [R_0402]  263.36 68.71 90 top
RE79  -  [R_0402]  276.19 64.09 270 top
RE81  -  [R_0402]  279.49 56.34 180 top
RE82  -  [R_0402]  279.49 55.45 180 top
RE83  -  [R_0402]  258.08 77.55 180 top
RE84  -  [R_0402]  260.11 76.46 270 top
RE85  -  [R_0402]  256.45 81.66 90 top
RE86  -  [R_0402]  255.6 61.36 90 top
RE88  -  [R_0402]  258.07 60.08 180 top
RE90  -  [R_0402]  130.1 88.6 270 bottom
RE274  -  [R_0402]  250.28 88.17 270 bottom
RE275  -  [R0402_0OHM]  249.39 88.17 270 bottom
RE277  -  [R_0402]  267.65 69.75 270 top
RE280  -  [R_0402]  257.92 63.99 180 top
RE288  -  [R_0402]  258.07 58.18 180 top
RE290  -  [R0402_0OHM]  269.25 53.65 0 top
RE292  -  [R_0402]  275.14 60.66 180 top
RE298  -  [R_0402]  261.2 75.65 270 top
RE299  -  [R_0402]  261.2 76.53 90 top
RE300  -  [R_0402]  276.19 66.37 270 top
RE301  -  [R_0402]  278.09 53.8 0 top
RE304  -  [R_0402]  228.21 79.54 180 top
RE305  -  [R0402_0OHM]  252.31 89.58 180 top
RE306  -  [R_0402]  252.01 93.79 270 top
RE308  -  [R_0402]  222.42 78.07 270 top
RE309  -  [R_0402]  257.69 84.75 90 bottom
RE310  -  [R_0402]  248.44 93.72 270 top
RE311  -  [R_0402]  249.33 93.72 270 top
RE312  -  [R_0402]  256.29 50.44 270 top
RE313  -  [R_0402]  260.56 51.62 270 top
RH359  -  [R_0402]  190.31 45.38 0 top
RI13  -  [R_0402]  280.86 63.21 90 bottom
RI14  -  [R_0402]  280.06 64.11 90 top
RI15  -  [R0402_0OHM]  286.04 60.15 0 top
RI16  -  [R0402_0OHM]  286.04 61.04 0 top
RI17  -  [R0402_0OHM]  286.06 58.35 0 top
RI18  -  [R0402_0OHM]  286.06 59.24 0 top
RI19  -  [R0402_0OHM]  19.9 77.47 90 bottom
RI20  -  [R0402_0OHM]  19.01 77.47 90 bottom
RI21  -  [R0402_0OHM]  21.68 77.47 90 bottom
RI22  -  [R0402_0OHM]  20.79 77.47 90 bottom
RI23  -  [R0402_0OHM]  66.45 92.13 90 top
RI24  -  [R0402_0OHM]  65.57 92.13 90 top
RI25  -  [R0402_0OHM]  68.24 92.13 90 top
RI26  -  [R0402_0OHM]  67.35 92.13 90 top
RI27  -  [R0402_0OHM]  233.51 72.04 270 top
RI28  -  [R0402_0OHM]  234.4 72.04 270 top
RI29  -  [R0402_0OHM]  236.82 70.95 270 top
RI30  -  [R0402_0OHM]  235.93 70.95 270 top
RI31  -  [R0402_0OHM]  243.46 68.88 270 top
RL1  -  [R_0402]  270.45 85.12 180 top
RL2  -  [R_0402]  270.45 85.98 180 top
RL3  -  [R0402_0OHM]  262.04 86.57 180 bottom
RL4  -  [R_0402]  259.29 92.46 90 top
RL5  -  [R_0402]  258.91 90.33 270 bottom
RL6  -  [R_0402]  257.16 92.13 0 top
RL7  -  [R0402_0OHM]  258.02 89.95 270 bottom
RL8  -  [R0603_0OHM]  255.1 89.81 270 bottom
RL9  -  [R_0402]  259.8 89.41 90 bottom
RL11  -  [R_0402]  258.66 84.48 270 top
RL12  -  [R_0402]  269.48 83.96 0 top
RL13  -  [R_0402]  260.74 82.53 270 top
RL14  -  [R_0402]  262.65 95.27 180 bottom
RL15  -  [R_0402]  269.43 94.91 270 top
RL16  -  [R_0402]  270.65 94.91 270 top
RL17  -  [R_0402]  276.6 94.94 270 top
RL18  -  [R_0402]  277.94 94.94 270 top
RL19  -  [R_0402]  286.35 91.3 90 bottom
RL20  -  [R_0402]  287.24 91.3 90 bottom
RL29  -  [R_0402]  274.26 71.84 90 top
RL30  -  [R_0402]  285.42 79.42 180 bottom
